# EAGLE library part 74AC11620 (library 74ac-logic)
Octal BUS TRANSCEIVER, 3-state
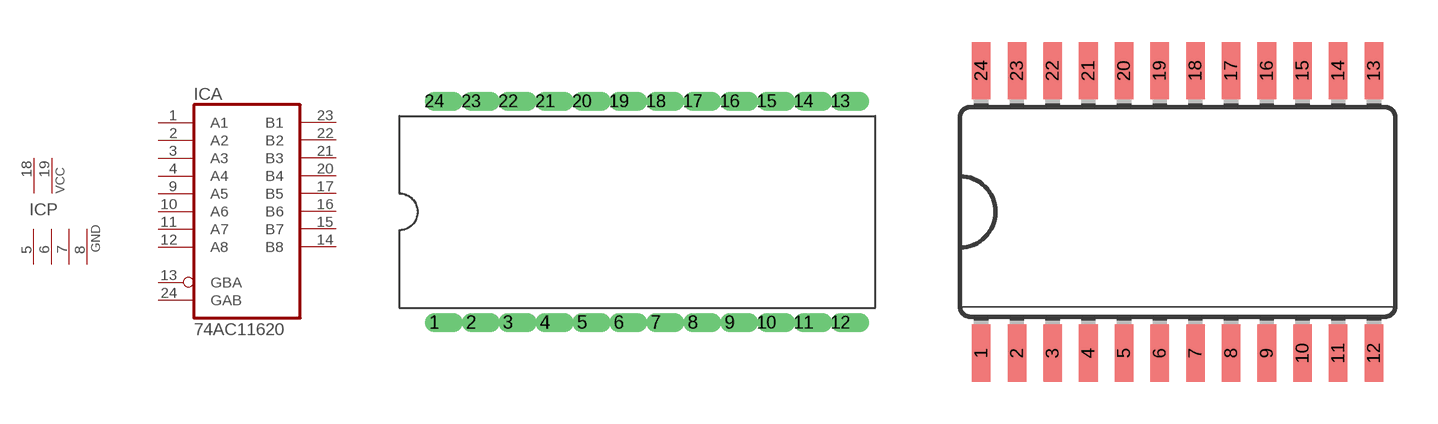
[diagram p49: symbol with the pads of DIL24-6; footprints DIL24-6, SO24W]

Designator prefix IC; gates A=7411620 P=2PWR4GND

## 74AC11620  [DIL24-6]
1  A:A1
2  A:A2
3  A:A3
4  A:A4
5  P:GND  pwr
6  P:GND  pwr
7  P:GND  pwr
8  P:GND  pwr
9  A:A5
10  A:A6
11  A:A7
12  A:A8
13  A:GBA  in
14  A:B8
15  A:B7
16  A:B6
17  A:B5
18  P:VCC  pwr
19  P:VCC  pwr
20  A:B4
21  A:B3
22  A:B2
23  A:B1
24  A:GAB  in

## 74AC11620D  [SO24W]
Pads as for DIL24-6

## Footprint DIL24-6 (pad centres in mm)
Dual In Line 0.6 inch
drill 0.813 offset: 1 -13.97,-7.62; 2 -11.43,-7.62; 3 -8.89,-7.62; 4 -6.35,-7.62; 5 -3.81,-7.62; 6 -1.27,-7.62; 7 1.27,-7.62; 8 3.81,-7.62; 9 6.35,-7.62; 10 8.89,-7.62; 11 11.43,-7.62; 12 13.97,-7.62; 13 13.97,7.62; 14 11.43,7.62; 15 8.89,7.62; 16 6.35,7.62; 17 3.81,7.62; 18 1.27,7.62; 19 -1.27,7.62; 20 -3.81,7.62; 21 -6.35,7.62; 22 -8.89,7.62; 23 -11.43,7.62; 24 -13.97,7.62

## Footprint SO24W (pad centres in mm)
Wide Small Outline package 300 mil
smd 0.66 x 2.032: 1 -6.985,-5.029; 2 -5.715,-5.029; 3 -4.445,-5.029; 4 -3.175,-5.029; 5 -1.905,-5.029; 6 -0.635,-5.029; 7 0.635,-5.029; 8 1.905,-5.029; 9 3.175,-5.029; 10 4.445,-5.029; 11 5.715,-5.029; 12 6.985,-5.029; 13 6.985,5.029; 14 5.715,5.029; 15 4.445,5.029; 16 3.175,5.029; 17 1.905,5.029; 18 0.635,5.029; 19 -0.635,5.029; 20 -1.905,5.029; 21 -3.175,5.029; 22 -4.445,5.029; 23 -5.715,5.029; 24 -6.985,5.029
